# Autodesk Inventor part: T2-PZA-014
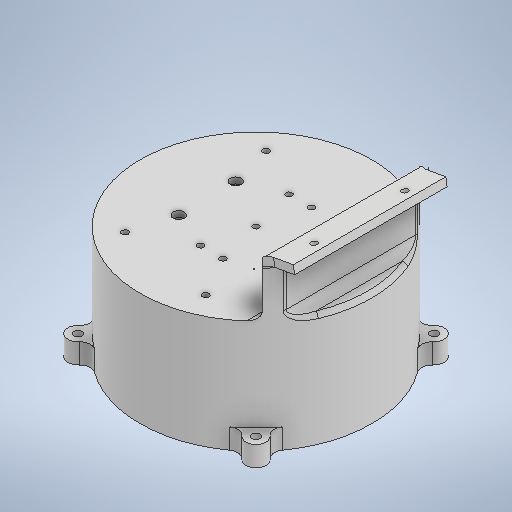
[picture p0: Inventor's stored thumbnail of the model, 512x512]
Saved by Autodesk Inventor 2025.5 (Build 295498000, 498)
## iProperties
Created: 2026-10
Part Number: T2-PZA-014
Material: Genérico
Document SubType Name: Modeling
Designer: Luis MuÃ±oz
Density: 1 g/cm^3
Appearance: Valor por defecto
Project: TESIS 2 - Plataforma mecatrÃ³nica preventiva desacoplada
Description: Carcasa del módulo electrónico
Material_Fabricacion: PLA
Author: Luis M
Title: Carcasa del mÃ³dulo electrÃ³nico
Revision Number: 00
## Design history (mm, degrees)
sketch "Boceto1"
  geometry: L1 (5.6, 22)-(-5.6, 22); L2 (-5.6, 22)-(-5.6, -22); L3 (-5.6, -22)-(5.6, -22); L4 (5.6, -22)-(5.6, 22); L5 (5.6, 22)-(-5.6, -22); L6 (-5.6, 22)-(5.6, -22); L7 (0, 0)-(35, 0); L8 (35, 0)-(35, 40); L9 (35, 40)-(0, 40); L10 (0, 40)-(0, 0); L11 (35, 40)-(-27, 40); L12 (-27, 40)-(-27, -40); L13 (-27, -40)-(35, -40); L14 (35, -40)-(35, 40); C1 r 1.55 at (0, 0); C2 r 1.55 at (5.6, -22); C3 r 1.55 at (-5.6, -22); C4 r 1.55 at (5.6, 22); C5 r 1.55 at (-5.6, 22); C6 r 60.5 at (0, 0); C7 r 62.5 at (0, 0); C8 r 1.55 at (35, -40); C9 r 1.55 at (35, 40); C10 r 1.55 at (-27, 40); C11 r 1.55 at (-27, -40); 1 further point
  constraints: 28 end point, 11 centre point, 11 coincident, 6 parallel, 3 horizontal, 3 perpendicular, 2 midpoint
  dimensions: "d0" = 44 distance of L3.end L1.start; "d1" = 11.2 distance of L1.start L1.end; "d2" = 3.1 diameter of C1; "d3" = 3.1 diameter of C2; "d4" = 3.1 diameter of C3; "d5" = 3.1 diameter of C4; "d6" = 3.1 diameter of C5; "d7" = 121 diameter of C6; "d11" = 35 distance of L9.end L8.end; "d12" = 40 distance of L8.end L7.end; "d13" = 62 distance of L13.end L12.end; "d14" = 80 distance of L12.end L11.end; "d15" = 3.1 diameter of C8; "d16" = 3.1 diameter of C9; "d17" = 3.1 diameter of C10; "d18" = 3.1 diameter of C11
extrude "Extrusión1" new body sketch "Boceto1" distance "d9" = 6; taper "d10" = 0 deg
extrude "Extrusión2" cut sketch "Boceto1" distance "d19" = 5; taper "d20" = 0 deg
sketch "Boceto2"
  geometry: C1 r 1.55 at (27, -40) reference; C2 r 1.55 at (-35, -40) reference; C3 r 1.55 at (27, 40) reference; C4 r 1.55 at (-35, 40) reference; C5 r 60.5 at (0, 0) reference; C6 r 1.55 at (5.6, 22) reference; C7 r 1.55 at (5.6, -22) reference; C8 r 1.55 at (-5.6, -22) reference; C9 r 1.55 at (0, 0) reference; C10 r 1.55 at (-5.6, 22) reference; C11 r 57.5 at (0, 0); 1 further point
  constraints: 1 centre point, 1 coincident
  dimensions: "d21" = 115 diameter of C11
extrude "Extrusión3" join sketch "Boceto2" distance "d22" = 30; taper "d23" = 0 deg
sketch "Boceto5"
  geometry: L1 (-30, -57.5)-(-30, 57.5) reference; L2 (0, 57.5)-(0, -57.5) reference; L3 (0, 0)-(-12, 0); L4 (-7, 15)-(-17, 15); L5 (-17, 15)-(-17, -15); L6 (-17, -15)-(-7, -15); L7 (-7, -15)-(-7, 15); L8 (-7, 15)-(-17, -15); L9 (-17, 15)-(-7, -15); L10 (-12, 15)-(-12, -15)
  constraints: 16 end point, 4 midpoint, 2 horizontal, 2 parallel, 1 perpendicular
  dimensions: "d28" = 12 distance of L3.start L3.end; "d29" = 10 distance of L6.end L5.end; "d30" = 30 distance of L5.end L4.end
extrude "Extrusión5" cut sketch "Boceto5" stored distance "d31" = 181; taper "d32" = 0 deg
sketch "Boceto6"
  geometry: L1 (47.204, 44.298)-(42.204, 44.298); L2 (42.204, 44.298)-(42.204, -44.298); L3 (42.204, -44.298)-(47.204, -44.298); L4 (47.204, -44.298)-(47.204, 44.298); L5 (47.204, 44.298)-(42.204, -44.298); L6 (42.204, 44.298)-(47.204, -44.298); C1 r 60.5 at (0, 0) reference; C2 r 1.55 at (5.6, -22) reference; C3 r 1.55 at (5.6, 22) reference; C4 r 1.55 at (-5.6, 22) reference; C5 r 1.55 at (0, 0) reference; C6 r 1.55 at (-5.6, -22) reference; 6 further points
  constraints: 12 end point, 2 midpoint, 2 parallel, 1 horizontal, 1 perpendicular
  dimensions: "d33" = 5 distance of L3.end L2.end
extrude "Extrusión6" join sketch "Boceto6" distance "d34" = 25; taper "d35" = 0 deg
node "Plano de trabajo1"
sketch "Boceto7"
  geometry: L1 (87.646, 4.924)-(0.949, 4.924) reference; L2 (6.455, 0)-(82.14, 0) reference; L3 (6.455, 0)-(82.14, 0); L4 (82.14, 0)-(82.14, -10); L5 (82.14, -10)-(6.455, -10); L6 (6.455, -10)-(6.455, 0); L7 (44.298, -10)-(44.298, 0); L8 (66.798, -5)-(21.798, -5); C1 r 1.6 at (21.798, -5); C2 r 1.6 at (66.798, -5); 11 further points; 3 other entities
  constraints: 12 end point, 4 midpoint, 2 centre point, 2 coincident, 2 horizontal, 2 parallel, 1 perpendicular, 4 other
  dimensions: "d37" = 10 distance of L3.end L4.end; "d38" = 45 distance of L8.start L8.end; "d39" = 3.2 diameter of C1; "d40" = 3.2 diameter of C2
extrude "Extrusión7" join sketch "Boceto7" distance "d41" = 4; taper "d42" = 0 deg
fillet "Empalme3" dims "d45" = 4
sketch "Boceto8"
  geometry: L1 (-40, 50)-(40, 50); L2 (40, 50)-(40, -50); L3 (40, -50)-(-40, -50); L4 (-40, -50)-(-40, 50); L5 (-40, 50)-(40, -50); L6 (40, 50)-(-40, -50); L7 (48.099, 51.331)-(38.216, 40.784); L8 (38.216, 40.784)-(40.703, 59.935); L9 (40.703, 59.935)-(31.476, 46.348); L10 (47.613, -50.812)-(37.845, -40.388); L11 (30.656, -46.324)-(43.643, -62.557); L12 (-42.321, -62.318)-(-29.416, -43.314); L13 (-52.517, -56.045)-(-40, -42.688); L14 (-42.805, 60.306)-(-29.501, 46.108); L15 (-37.445, 39.961)-(-48.012, 51.238); C1 r 60.5 at (0, 0) reference; C2 r 57.5 at (0, 0) reference; C3 r 1.55 at (0, 0) reference; C4 r 2 at (40, 50); C5 r 2 at (40, -50); C6 r 2 at (-40, -50); C7 r 2 at (-40, 50); C8 r 5 at (40, 50); C9 r 5 at (40, -50); C10 r 5 at (-40, -50); C11 r 5 at (-40, 50); 18 further points
  constraints: 30 end point, 8 centre point, 8 coincident, 8 tangent, 6 line through centre, 3 parallel, 2 midpoint, 1 horizontal, 1 perpendicular, 1 point on line
  dimensions: "d46" = 80 distance of L2.end L3.end; "d47" = 100 distance of L1.end L2.end; "d48" = 4 diameter of C4; "d49" = 4 diameter of C5; "d50" = 4 diameter of C6; "d51" = 4 diameter of C7; "d52" = 10 diameter of C8; "d53" = 10 diameter of C9; "d54" = 10 diameter of C10; "d55" = 10 diameter of C11
extrude "Extrusión8" join sketch "Boceto8" distance "d56" = 10; taper "d57" = 0 deg
sketch "Boceto11"
  geometry: L1 (41.368, 44.147)-(43.649, 46.581) reference; L2 (35.864, 52.809)-(33.99, 50.05) reference; L3 (-33.502, 50.377)-(-36.351, 53.419) reference; L4 (-43.649, 46.581)-(-41.368, 44.147) reference; L5 (-41.368, -44.147)-(-43.649, -46.581) reference; L6 (-35.864, -52.809)-(-33.99, -50.05) reference; L7 (33.76, -50.204)-(36.096, -53.123) reference; L8 (43.649, -46.581)-(41.368, -44.147) reference; C1 r 40 at (0, 0); C2 r 57.5 at (0, 0); C3 r 81.97 at (6.395, 2.433); C4 r 2 at (40, 50) reference; C5 r 2 at (40, -50) reference; C6 r 2 at (-40, 50) reference; C7 r 2 at (-40, -50) reference; C8 r 57.5 at (0, 0) reference; A1 r 60.5 centre (0, 0) between (41.368, -44.147) and (41.368, 44.147) reference; A2 r 60.5 centre (0, 0) between (41.368, -44.147) and (41.368, 44.147) reference; A3 r 5 centre (40, 50) between (43.649, 46.581) and (35.864, 52.809) reference; A4 r 60.5 centre (0, 0) between (33.99, 50.05) and (-33.502, 50.377) reference; A5 r 5 centre (-40, 50) between (-36.351, 53.419) and (-43.649, 46.581) reference; A6 r 60.5 centre (0, 0) between (-41.368, 44.147) and (-41.368, -44.147) reference; A7 r 5 centre (-40, -50) between (-43.649, -46.581) and (-35.864, -52.809) reference; A8 r 60.5 centre (0, 0) between (-33.99, -50.05) and (33.76, -50.204) reference; A9 r 5 centre (40, -50) between (36.096, -53.123) and (43.649, -46.581) reference; A10 r 60.5 centre (0, 0) between (41.368, 44.147) and (33.99, 50.05) reference; A11 r 60.5 centre (0, 0) between (33.76, -50.204) and (41.368, -44.147) reference; A12 r 60.5 centre (0, 0) between (-41.368, -44.147) and (-33.99, -50.05) reference; A13 r 60.5 centre (0, 0) between (-33.502, 50.377) and (-41.368, 44.147) reference; 1 further point
  constraints: 3 centre point, 2 coincident
  dimensions: "d60" = 80 diameter of C1; "d61" = 115 diameter of C2
  node "Contorno proyectado8"
extrude "Extrusión9" cut sketch "Boceto11" distance "d62" = 78.5; taper "d63" = 0 deg
extrude "Extrusión10" join sketch "Boceto11" distance "d64" = 50; taper "d65" = 0 deg
sketch "Boceto12"
  geometry: C1 r 57.5 at (0, 0) reference; C2 r 1.55 at (27, -40) reference; C3 r 1.55 at (-35, -40) reference; C4 r 1.55 at (27, 40) reference; C5 r 1.55 at (-35, 40) reference; C6 r 1.55 at (5.6, 22) reference; C7 r 1.55 at (5.6, -22) reference; C8 r 1.55 at (-5.6, -22) reference; C9 r 1.55 at (0, 0) reference; C10 r 1.55 at (-5.6, 22) reference; 1 further point
extrude "Extrusión11" join sketch "Boceto12" stored distance "d66" = 50; taper "d67" = 0 deg
sketch "Boceto13"
  geometry: C1 r 1.6 at (17, 42); C2 r 1.6 at (35, -30); C3 r 1.6 at (-30, 35); C4 r 1.6 at (-30, -35); C5 r 57.5 at (0, 0) reference; C6 r 1.55 at (5.6, 22) reference; C7 r 1.55 at (5.6, -22) reference; C8 r 1.55 at (-5.6, -22) reference; C9 r 1.55 at (0, 0) reference; C10 r 1.55 at (-5.6, 22) reference; 1 further point
  constraints: 4 centre point
  dimensions: "d68" = 3.2 diameter of C1; "d69" = 3.2 diameter of C2; "d70" = 3.2 diameter of C3; "d71" = 3.2 diameter of C4; "d72" = 17 horizontal distance of point (0, 0) C1.centre; "d73" = 42 vertical distance of C1.centre point (0, 0); "d74" = 35 horizontal distance of point (0, 0) C2.centre; "d75" = 30 vertical distance of point (0, 0) C2.centre; "d76" = 35 vertical distance of point (0, 0) C4.centre; "d77" = 35 vertical distance of C3.centre point (0, 0); "d78" = 30 horizontal distance of point (0, 0) C3.centre; "d79" = 30 horizontal distance of C4.centre point (0, 0)
extrude "Extrusión12" cut sketch "Boceto13" distance "d80" = 65.25; taper "d81" = 0 deg
sketch "Boceto14"
  geometry: L1 (24.4, -14.4)-(-24.4, -14.4); L2 (24.4, 14.4)-(-24.1, 14.3); C1 r 1.6 at (24.4, 14.4); C2 r 1.6 at (24.4, -14.4); C3 r 1.6 at (-24.4, -14.4); C4 r 1.6 at (-24.1, 14.3); 1 further point
  constraints: 4 centre point, 4 end point, 1 horizontal
  dimensions: "d82" = 3.2 diameter of C1; "d83" = 3.2 diameter of C2; "d84" = 3.2 diameter of C3; "d85" = 3.2 diameter of C4; "d86" = 48.8 distance of L1.end L1.start; "d87" = 48.5 horizontal distance of L2.start L2.end; "d88" = 28.8 distance of L2.start L1.start; "d89" = 28.7 vertical distance of L2.end L1.end; "d90" = 0 horizontal distance of L2.start L1.start; "d91" = 24.4 horizontal distance of point (0, 0) L2.start; "d92" = 14.4 distance from line of L1 point (0, 0)
extrude "Extrusión13" cut sketch "Boceto14" distance "d93" = 111; taper "d94" = 0 deg
sketch "Boceto15"
  geometry: L1 (38.204, 46.912)-(38.204, -46.912) reference; C1 r 1.6 at (-24.4, 14.4) reference; C2 r 1.6 at (24.4, -14.4) reference; C3 r 1.6 at (-24.1, -14.3) reference; C4 r 1.6 at (24.4, 14.4) reference; C5 r 1.6 at (-30, -35) reference; C6 r 1.6 at (17, -42) reference; C7 r 1.6 at (-30, 35) reference; C8 r 1.6 at (35, 30) reference; C9 r 1.55 at (-5.6, -22) reference; C10 r 1.55 at (0, 0) reference; C11 r 1.55 at (-5.6, 22) reference; C12 r 1.55 at (5.6, 22) reference; C13 r 1.55 at (5.6, -22) reference; C14 r 2.75 at (24.4, 14.4); C15 r 2.75 at (24.4, -14.4); C16 r 2.75 at (-24.1, -14.3); C17 r 2.75 at (-24.4, 14.4); A1 r 60.5 centre (0, 0) between (38.204, 46.912) and (38.204, -46.912) reference; 1 further point
  constraints: 4 centre point, 4 coincident
  dimensions: "d95" = 5.5 diameter of C14; "d96" = 5.5 diameter of C15; "d97" = 5.5 diameter of C16; "d98" = 5.5 diameter of C17
extrude "Extrusión14" cut sketch "Boceto15" distance "d99" = 3; taper "d100" = 0 deg
sketch "Boceto16"
  geometry: C1 r 1.6 at (-24.4, -14.4) reference; C2 r 1.6 at (24.4, 14.4) reference; C3 r 1.6 at (-24.1, 14.3) reference; C4 r 1.6 at (24.4, -14.4) reference; C5 r 1.6 at (-30, 35) reference; C6 r 1.6 at (17, 42) reference; C7 r 1.6 at (-30, -35) reference; C8 r 1.6 at (35, -30) reference; C9 r 57.5 at (0, 0) reference; C10 r 1.55 at (5.6, 22) reference; C11 r 1.55 at (5.6, -22) reference; C12 r 1.55 at (-5.6, -22) reference; C13 r 1.55 at (0, 0) reference; C14 r 1.55 at (-5.6, 22) reference; C15 r 52.5 at (0, 0); C16 r 57.5 at (0, 0); C17 r 60.5 at (0, 0); 1 further point
  constraints: 3 centre point, 3 coincident, 1 concentric
  dimensions: "d101" = 105 diameter of C15
  node "Contorno proyectado12"
extrude "Extrusión15" cut sketch "Boceto16" stored distance "d102" = 76.75; taper "d103" = 0 deg
extrude "Extrusión16" join sketch "Boceto16" stored distance "d104" = 10; taper "d105" = 0 deg
sketch "Boceto17"
  geometry: 1 further point
sketch "Boceto18"
  geometry: L1 (-4.924, -1.096)-(-4.924, -0.949) reference; L2 (-5.077, -5.245)-(-5.077, -0.949) reference; L3 (0, -11.464)-(0, -77.132) reference; L4 (-5.077, -87.646)-(-5.077, -83.35) reference; L5 (-4.924, -87.646)-(-4.924, -87.499) reference; L6 (10, -82.14)-(0, -82.14) reference; L7 (10, -6.455)-(10, -82.14) reference; L8 (0, -6.455)-(10, -6.455) reference; L9 (0, -6.455)-(-5.077, -5.245); L10 (0, -82.14)-(-5.077, -83.35); C1 r 1.6 at (5, -21.798) reference; C2 r 1.6 at (5, -66.798) reference; 8 further points; 5 other entities
  constraints: 4 end point, 6 other
extrude "Extrusión17" cut sketch "Boceto18" distance "d106" = 10; taper "d107" = 0 deg
fillet "Empalme6" dims "d108" = 2
fillet "Empalme7" dims "d109" = 3
fillet "Empalme8" dims "d110" = 2
sketch "Boceto19" dims "d111" = 125
  geometry: L1 (0, 0)-(0, -46.545); L2 (44.194, -44.194)-(0, 0); L3 (52.406, 44.619)-(36.299, 30.905); L4 (36.299, 30.905)-(30.615, 35.958); L5 (30.615, 35.958)-(44.046, 51.733); L6 (49.862, -42.453)-(38.677, -32.93); L7 (38.677, -32.93)-(32.252, -37.881); L8 (32.252, -37.881)-(47.476, -55.761); L9 (-49.391, -58.011)-(-32.872, -38.609); L10 (-32.872, -38.609)-(-38.251, -32.567); L11 (-38.251, -32.567)-(-52.984, -45.111); L12 (-45.129, 53.005)-(-31.106, 36.534); L13 (-31.106, 36.534)-(-34.122, 29.052); L14 (-34.122, 29.052)-(-50.916, 43.35); C1 r 57.5 at (0, 0) reference; C2 r 52.5 at (0, 0) reference; C3 r 1.55 at (0, 0) reference; C4 r 2 at (44.194, -44.194); C5 r 2 at (44.194, 44.194); C6 r 2 at (-44.194, 44.194); C7 r 2 at (-44.194, -44.194); C8 r 5 at (44.194, 44.194); C9 r 5 at (44.194, -44.194); C10 r 5 at (-44.194, -44.194); C11 r 5 at (-44.194, 44.194); 18 further points
  constraints: 28 end point, 11 tangent, 8 centre point, 8 line through centre, 5 coincident, 1 vertical, 12 other
  dimensions: "d112" = 4 diameter of C4; "d115" = 360 deg dimension on point (0, 0) L2.start (derived); "d117" = 45 deg angle of L2 L1; "d118" = 10 diameter of C9
extrude "Extrusión18" join sketch "Boceto19" distance "d119" = 10; taper "d120" = 0 deg
fillet "Empalme9" dims "d121" = 5
node "Sólido1"
node "Contorno proyectado1"
node "Contorno proyectado3"
node "Contorno proyectado4"
node "Contorno proyectado5"
node "Contorno proyectado6"
node "Contorno proyectado9"
node "Contorno proyectado10"
node "Contorno proyectado11"
node "Contorno proyectado13"
node "Contorno proyectado14"
node "Boceto - Patrón circular1" dims "d115" = 360 deg (derived)
other parameters: "d36" = -100 deg
